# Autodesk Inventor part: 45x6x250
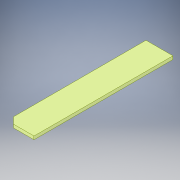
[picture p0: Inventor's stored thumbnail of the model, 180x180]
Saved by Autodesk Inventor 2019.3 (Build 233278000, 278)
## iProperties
Created: 2019-02
Part Number: 45x6x250
Material: Ocel, měkká, svařovaná
Document SubType Name: Modeling
Designer: B-hon
Density: 7.85 g/cm^3
Appearance: Zinek – chromovaný 2
Author: B-hon
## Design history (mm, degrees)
sketch "Náčrt1"
  geometry: L1 (-25, 3)-(25, 3); L2 (25, 3)-(25, -3); L3 (25, -3)-(-25, -3); L4 (-25, -3)-(-25, 3); L5 (-25, 3)-(25, -3); L6 (25, 3)-(-25, -3); 1 further point
  constraints: 12 end point, 2 midpoint, 2 parallel, 1 horizontal, 1 perpendicular
  dimensions: "d0" = 50 distance of L2.end L3.end; "d1" = 6 distance of L1.end L2.end
extrude "Vysunutí1" new body sketch "Náčrt1" distance "d2" = 258; taper "d3" = 0 deg
chamfer "Zkosení2" distance "d7" = 12; stored, may be unused: second distance "d8" = 2, angle "d9" = 45 deg
node "Těleso1"
